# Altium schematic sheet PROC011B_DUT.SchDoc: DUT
size 431 x 279 mm; Date: Not shown in title block; ApprovedBy: Not shown in title block; CheckedBy: Not shown in title block; Author: Not shown in title block; CompanyName: Not shown in title block; Engineer: Not shown in title block; Organization: Not shown in title block; Address1: Not shown in title block; Address2: Not shown in title block; Address3: Not shown in title block; Address4: Not shown in title block; DocumentNumber: 1; Revision: Use project parameter SCH_Rev; SheetNumber: 2; SheetTotal: 17; PageSetup: Record=PageOptions¦CenterHorizontal=True¦CenterVertical=True¦PrintScale=0.64¦XCorrection=1.00¦YCorrection=1.00¦PrintKind=0¦BorderSize=5000000¦LeftOffset=0¦BottomOffset=0¦Orientation=2¦PaperLength=1000¦PaperWidth=1000¦Scale=100¦PaperSource=15¦PrintQuality=600¦MediaType=1¦DitherType=10¦PrintScaleMode=1¦PaperKind=Letter
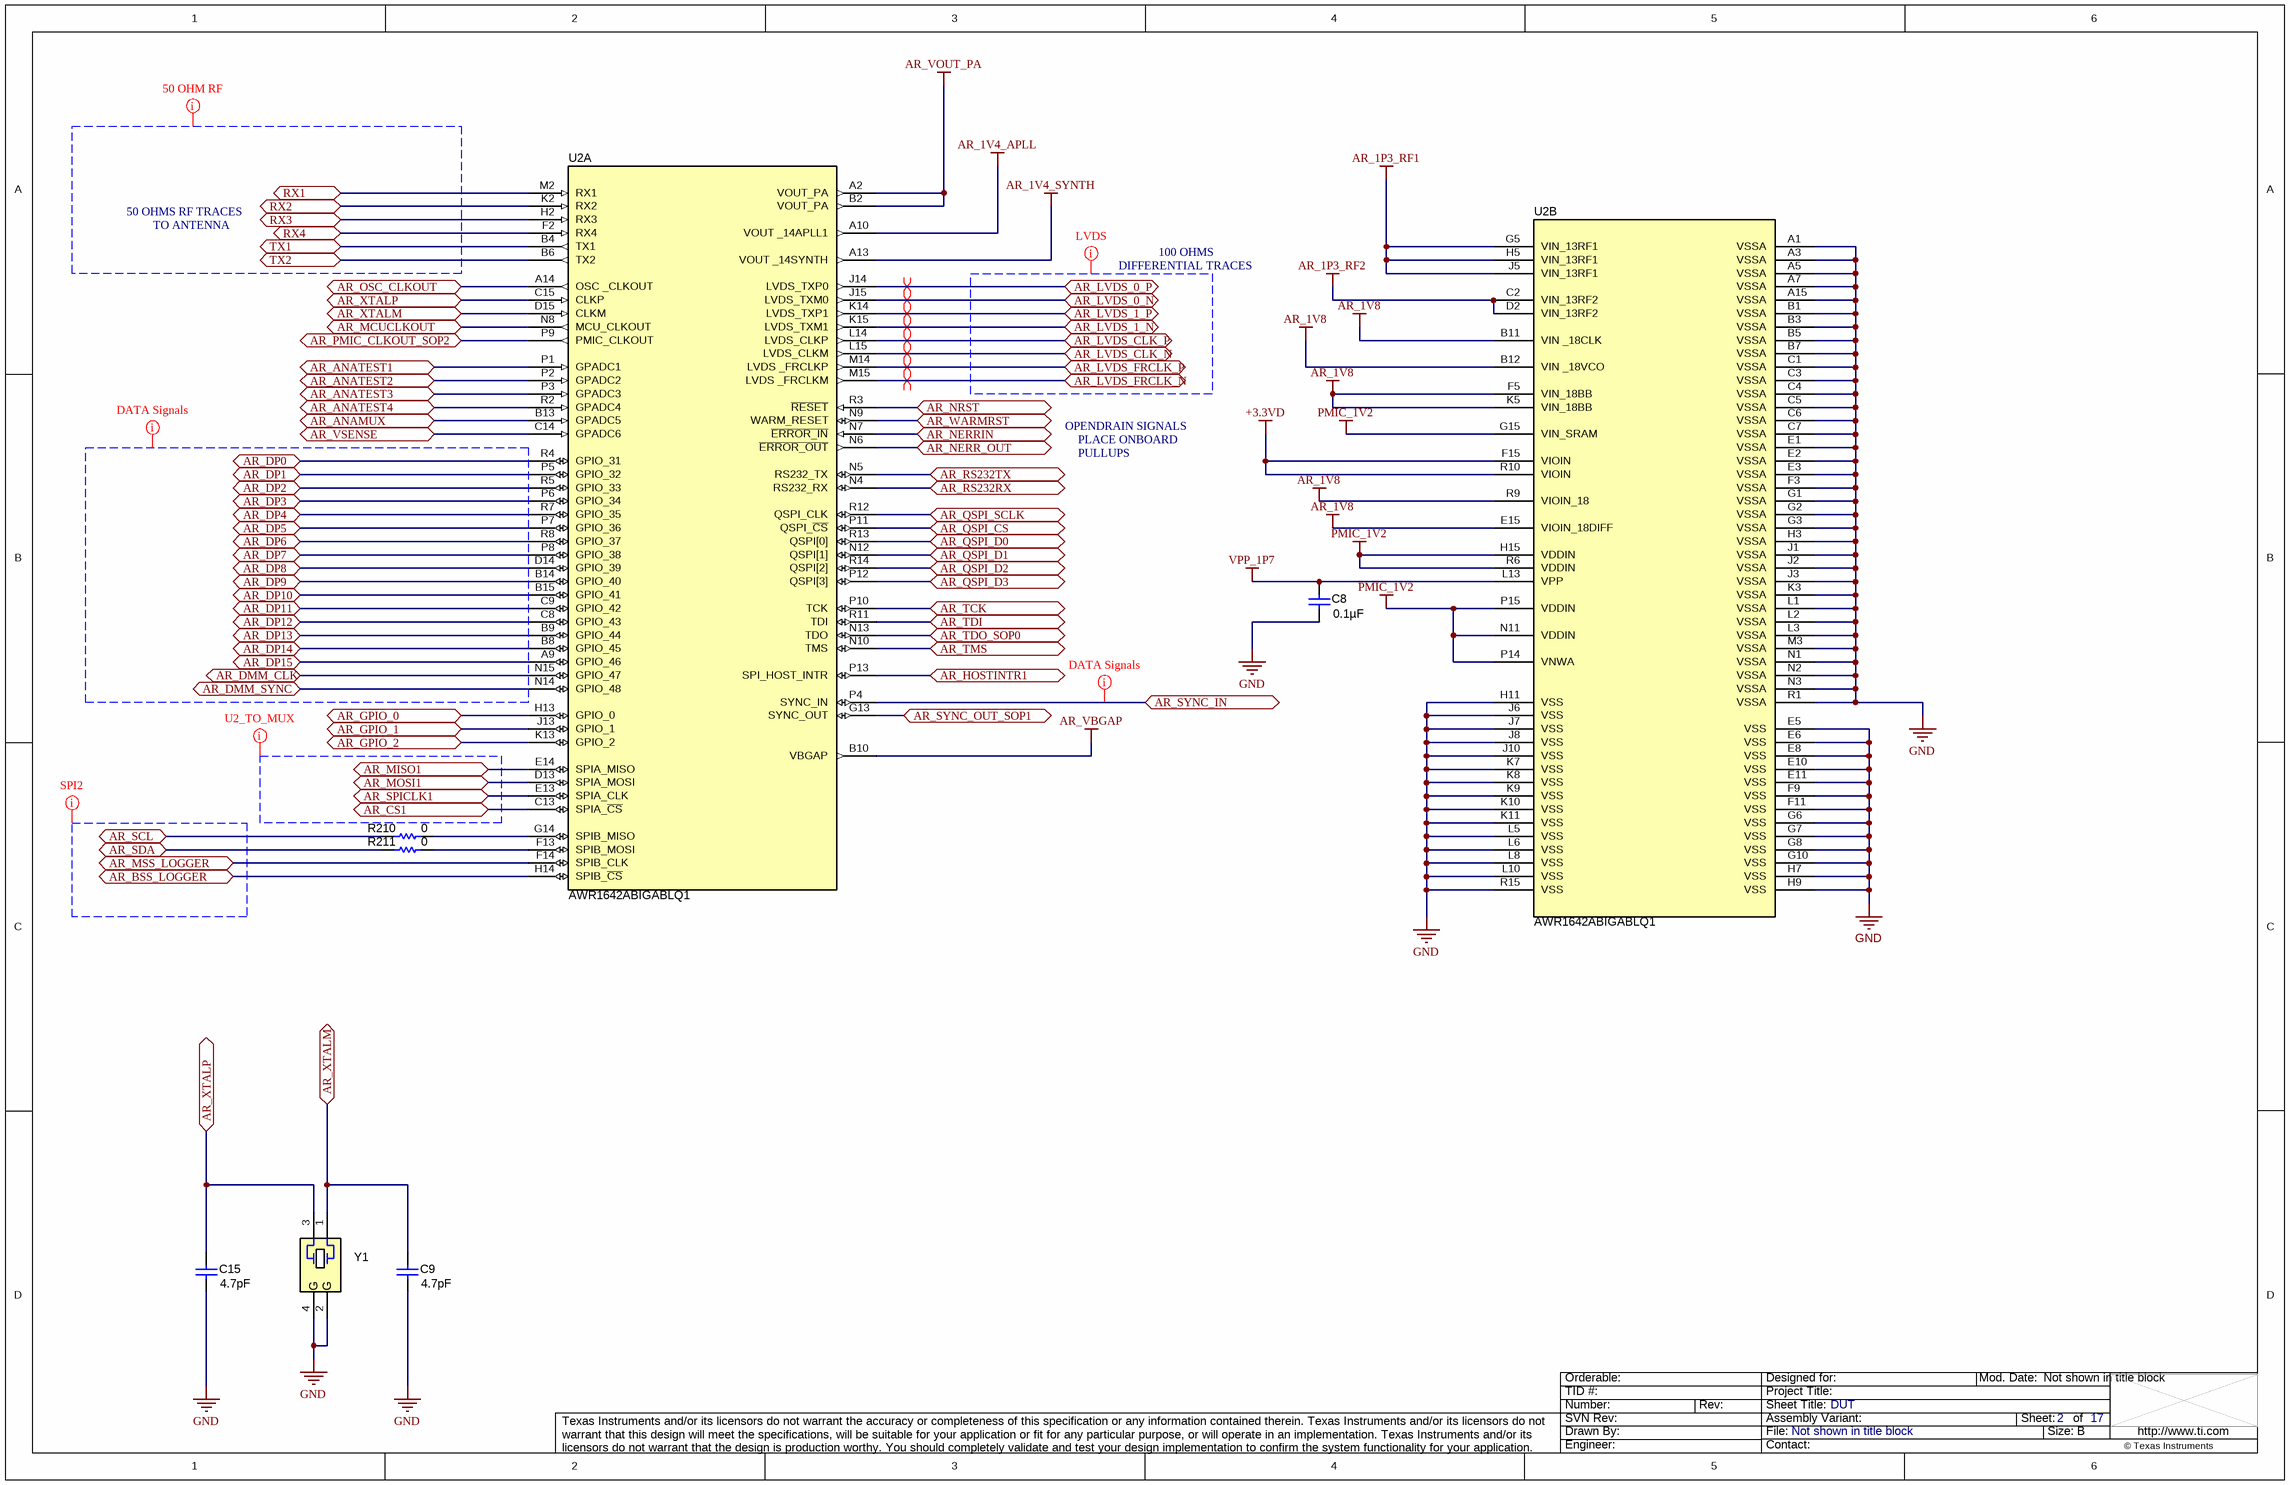
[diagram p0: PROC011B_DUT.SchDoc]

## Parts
C8  ValueDisplayed: 0.1µF  [0201_033]  (hidden comment: C0603X7S1A104K030BC)
C9  ValueDisplayed: 4.7pF  [0402L]  (hidden comment: GJM1555C1H4R7BB01D)
C15  ValueDisplayed: 4.7pF  [0402L]  (hidden comment: GJM1555C1H4R7BB01D)
R210  ValueDisplayed: 0  [0201]  (hidden comment: CRCW02010000Z0ED)
R211  ValueDisplayed: 0  [0201]  (hidden comment: CRCW02010000Z0ED)
U2  PartNumber: AWR1642ABIGABLQ1  [ABL0161B]  (hidden comment: X1642BIGABL)  (parts A,B of 2)
Y1  CX3225SA40000D0PTWCC  [Kyocera_CX3225SA]  (value not drawn)

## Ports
AR_ANAMUX, AR_ANATEST1, AR_ANATEST2, AR_ANATEST3, AR_ANATEST4, AR_BSS_LOGGER, AR_CS1, AR_DMM_CLK, AR_DMM_SYNC, AR_DP0, AR_DP1, AR_DP2, AR_DP3, AR_DP4, AR_DP5, AR_DP6, AR_DP7, AR_DP8, AR_DP9, AR_DP10, AR_DP11, AR_DP12, AR_DP13, AR_DP14, AR_DP15, AR_GPIO_0, AR_GPIO_1, AR_GPIO_2, AR_HOSTINTR1, AR_LVDS_0_N, AR_LVDS_0_P, AR_LVDS_1_N, AR_LVDS_1_P, AR_LVDS_CLK_N, AR_LVDS_CLK_P, AR_LVDS_FRCLK_N, AR_LVDS_FRCLK_P, AR_MCUCLKOUT, AR_MISO1, AR_MOSI1, AR_MSS_LOGGER, AR_NERR_OUT, AR_NERRIN, AR_NRST, AR_OSC_CLKOUT, AR_PMIC_CLKOUT_SOP2, AR_QSPI_CS, AR_QSPI_D0, AR_QSPI_D1, AR_QSPI_D2, AR_QSPI_D3, AR_QSPI_SCLK, AR_RS232RX, AR_RS232TX, AR_SCL, AR_SDA, AR_SPICLK1, AR_SYNC_IN, AR_SYNC_OUT_SOP1, AR_TCK, AR_TDI, AR_TDO_SOP0, AR_TMS, AR_VSENSE, AR_WARMRST, AR_XTALM, AR_XTALP, RX1, RX2, RX3, RX4, TX1, TX2

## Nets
+3.3VD: U2.F15(VIOIN) U2.R10(VIOIN)
AR_1P3_RF1: U2.G5(VIN_13RF1) U2.H5(VIN_13RF1) U2.J5(VIN_13RF1)
AR_1P3_RF2: U2.C2(VIN_13RF2) U2.D2(VIN_13RF2)
AR_1V4_APLL: U2.A10(VOUT__14APLL1)
AR_1V4_SYNTH: U2.A13(VOUT__14SYNTH)
AR_1V8: U2.B11(VIN__18CLK) U2.B12(VIN__18VCO) U2.E15(VIOIN_18DIFF) U2.F5(VIN_18BB) U2.K5(VIN_18BB) U2.R9(VIOIN_18)
AR_VBGAP: U2.B10(VBGAP)
AR_VOUT_PA: U2.A2(VOUT_PA) U2.B2(VOUT_PA)
GND: C8.1 C9.1 C15.1 U2.A1(VSSA) U2.A3(VSSA) U2.A5(VSSA) U2.A7(VSSA) U2.A15(VSSA) U2.B1(VSSA) U2.B3(VSSA) U2.B5(VSSA) U2.B7(VSSA) U2.C1(VSSA) U2.C3(VSSA) U2.C4(VSSA) U2.C5(VSSA) U2.C6(VSSA) U2.C7(VSSA) U2.E1(VSSA) U2.E2(VSSA) U2.E3(VSSA) U2.E5(VSS) U2.E6(VSS) U2.E8(VSS) U2.E10(VSS) U2.E11(VSS) U2.F3(VSSA) U2.F9(VSS) U2.F11(VSS) U2.G1(VSSA) U2.G2(VSSA) U2.G3(VSSA) U2.G6(VSS) U2.G7(VSS) U2.G8(VSS) U2.G10(VSS) U2.H3(VSSA) U2.H7(VSS) U2.H9(VSS) U2.H11(VSS) U2.J1(VSSA) U2.J2(VSSA) U2.J3(VSSA) U2.J6(VSS) U2.J7(VSS) U2.J8(VSS) U2.J10(VSS) U2.K3(VSSA) U2.K7(VSS) U2.K8(VSS) U2.K9(VSS) U2.K10(VSS) U2.K11(VSS) U2.L1(VSSA) U2.L2(VSSA) U2.L3(VSSA) U2.L5(VSS) U2.L6(VSS) U2.L8(VSS) U2.L10(VSS) U2.M3(VSSA) U2.N1(VSSA) U2.N2(VSSA) U2.N3(VSSA) U2.R1(VSSA) U2.R15(VSS) Y1.2(GND) Y1.4(GND)
PMIC_1V2: U2.G15(VIN_SRAM) U2.H15(VDDIN) U2.N11(VDDIN) U2.P14(VNWA) U2.P15(VDDIN) U2.R6(VDDIN)
VPP_1P7: C8.2 U2.L13(VPP)
AR_ANAMUX: U2.B13(GPADC5) ; port AR_ANAMUX
AR_ANATEST1: U2.P1(GPADC1) ; port AR_ANATEST1
AR_ANATEST2: U2.P2(GPADC2) ; port AR_ANATEST2
AR_ANATEST3: U2.P3(GPADC3) ; port AR_ANATEST3
AR_ANATEST4: U2.R2(GPADC4) ; port AR_ANATEST4
AR_BSS_LOGGER: U2.H14(SPIB_~{CS}) ; port AR_BSS_LOGGER
AR_CS1: U2.C13(SPIA_~{CS}) ; port AR_CS1
AR_DMM_CLK: U2.N15(GPIO_47) ; port AR_DMM_CLK
AR_DMM_SYNC: U2.N14(GPIO_48) ; port AR_DMM_SYNC
AR_DP0: U2.R4(GPIO_31) ; port AR_DP0
AR_DP1: U2.P5(GPIO_32) ; port AR_DP1
AR_DP2: U2.R5(GPIO_33) ; port AR_DP2
AR_DP3: U2.P6(GPIO_34) ; port AR_DP3
AR_DP4: U2.R7(GPIO_35) ; port AR_DP4
AR_DP5: U2.P7(GPIO_36) ; port AR_DP5
AR_DP6: U2.R8(GPIO_37) ; port AR_DP6
AR_DP7: U2.P8(GPIO_38) ; port AR_DP7
AR_DP8: U2.D14(GPIO_39) ; port AR_DP8
AR_DP9: U2.B14(GPIO_40) ; port AR_DP9
AR_DP10: U2.B15(GPIO_41) ; port AR_DP10
AR_DP11: U2.C9(GPIO_42) ; port AR_DP11
AR_DP12: U2.C8(GPIO_43) ; port AR_DP12
AR_DP13: U2.B9(GPIO_44) ; port AR_DP13
AR_DP14: U2.B8(GPIO_45) ; port AR_DP14
AR_DP15: U2.A9(GPIO_46) ; port AR_DP15
AR_GPIO_0: U2.H13(GPIO_0) ; port AR_GPIO_0
AR_GPIO_1: U2.J13(GPIO_1) ; port AR_GPIO_1
AR_GPIO_2: U2.K13(GPIO_2) ; port AR_GPIO_2
AR_HOSTINTR1: U2.P13(SPI_HOST_INTR) ; port AR_HOSTINTR1
AR_LVDS_0_N: U2.J15(LVDS_TXM0) ; port AR_LVDS_0_N
AR_LVDS_0_P: U2.J14(LVDS_TXP0) ; port AR_LVDS_0_P
AR_LVDS_1_N: U2.K15(LVDS_TXM1) ; port AR_LVDS_1_N
AR_LVDS_1_P: U2.K14(LVDS_TXP1) ; port AR_LVDS_1_P
AR_LVDS_CLK_N: U2.L15(LVDS_CLKM) ; port AR_LVDS_CLK_N
AR_LVDS_CLK_P: U2.L14(LVDS_CLKP) ; port AR_LVDS_CLK_P
AR_LVDS_FRCLK_N: U2.M15(LVDS__FRCLKM) ; port AR_LVDS_FRCLK_N
AR_LVDS_FRCLK_P: U2.M14(LVDS__FRCLKP) ; port AR_LVDS_FRCLK_P
AR_MCUCLKOUT: U2.N8(MCU_CLKOUT) ; port AR_MCUCLKOUT
AR_MISO1: U2.E14(SPIA_MISO) ; port AR_MISO1
AR_MOSI1: U2.D13(SPIA_MOSI) ; port AR_MOSI1
AR_MSS_LOGGER: U2.F14(SPIB_CLK) ; port AR_MSS_LOGGER
AR_NERR_OUT: U2.N6(~{ERROR_OUT}) ; port AR_NERR_OUT
AR_NERRIN: U2.N7(~{ERROR_IN}) ; port AR_NERRIN
AR_NRST: U2.R3(~{RESET}) ; port AR_NRST
AR_OSC_CLKOUT: U2.A14(OSC__CLKOUT) ; port AR_OSC_CLKOUT
AR_PMIC_CLKOUT_SOP2: U2.P9(PMIC_CLKOUT) ; port AR_PMIC_CLKOUT_SOP2
AR_QSPI_CS: U2.P11(QSPI_~{CS}) ; port AR_QSPI_CS
AR_QSPI_D0: U2.R13(QSPI[0]) ; port AR_QSPI_D0
AR_QSPI_D1: U2.N12(QSPI[1]) ; port AR_QSPI_D1
AR_QSPI_D2: U2.R14(QSPI[2]) ; port AR_QSPI_D2
AR_QSPI_D3: U2.P12(QSPI[3]) ; port AR_QSPI_D3
AR_QSPI_SCLK: U2.R12(QSPI_CLK) ; port AR_QSPI_SCLK
AR_RS232RX: U2.N4(RS232_RX) ; port AR_RS232RX
AR_RS232TX: U2.N5(RS232_TX) ; port AR_RS232TX
AR_SCL: R210.1 ; port AR_SCL
AR_SDA: R211.1 ; port AR_SDA
AR_SPICLK1: U2.E13(SPIA_CLK) ; port AR_SPICLK1
AR_SYNC_IN: U2.P4(SYNC_IN) ; port AR_SYNC_IN
AR_SYNC_OUT_SOP1: U2.G13(SYNC_OUT) ; port AR_SYNC_OUT_SOP1
AR_TCK: U2.P10(TCK) ; port AR_TCK
AR_TDI: U2.R11(TDI) ; port AR_TDI
AR_TDO_SOP0: U2.N13(TDO) ; port AR_TDO_SOP0
AR_TMS: U2.N10(TMS) ; port AR_TMS
AR_VSENSE: U2.C14(GPADC6) ; port AR_VSENSE
AR_WARMRST: U2.N9(WARM_RESET) ; port AR_WARMRST
AR_XTALM: C9.2 U2.D15(CLKM) Y1.1 ; port AR_XTALM
AR_XTALP: C15.2 U2.C15(CLKP) Y1.3 ; port AR_XTALP
RX1: U2.M2(RX1) ; port RX1
RX2: U2.K2(RX2) ; port RX2
RX3: U2.H2(RX3) ; port RX3
RX4: U2.F2(RX4) ; port RX4
TX1: U2.B4(TX1) ; port TX1
TX2: U2.B6(TX2) ; port TX2
NetR210_2: R210.2 U2.G14(SPIB_MISO)
NetR211_2: R211.2 U2.F13(SPIB_MOSI)

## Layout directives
differential pair: AR_LVDS_0_N, AR_LVDS_0_P, AR_LVDS_1_N, AR_LVDS_1_P, AR_LVDS_CLK_N, AR_LVDS_CLK_P, AR_LVDS_FRCLK_N, AR_LVDS_FRCLK_P
net class LVDS: (no net found under the mark)
net class DATA0-15: (no net found under the mark), AR_SYNC_IN
net class RF_RX&TX: (no net found under the mark)
net class SPI2: (no net found under the mark)
net class U2_TO_MUX: (no net found under the mark)

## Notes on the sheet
- 50 OHMS RF TRACES
- TO ANTENNA
- DIFFERENTIAL TRACES
- 100 OHMS
- OPENDRAIN SIGNALS
- PLACE ONBOARD
- PULLUPS

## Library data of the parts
C8 = CMP-0078219-1: CAP, CERM, 0.1 µF, 10 V,+/- 10%, X7S, 0201; Manufacturer: TDK; TaMin_C: -55°C; Polarized: N; Green_Lifecycle: NRND; SizeAreaWB_mm2: 2.08; Green_REACh: Passed; U/M: EA; Value: 0.1uF; TaMax_C: 125°C; SizeZ_mm: 0.33; SizeX_mm: 0.6; SizeY_mm: 0.3; Cap_Case: 0201; Value2: 10V; SizeArea_mm2: 0.18; CompType: Capacitor; Cap_F: 100nF; AEC Category: Q200
C9 C15 = CMP-0006367-2: CAP, CERM, 4.7 pF, 50 V, +/- 2%, C0G/NP0, 0402; Manufacturer: MuRata; TaMin_C: -55°C; Polarized: N; SizeAreaWB_mm2: 3; Value1: Unknown; U/M: EA; Value: 4.7pF; TaMax_C: 125°C; SizeZ_mm: 0.6; SizeX_mm: 1; SizeY_mm: 0.5; Cap_Case: 0402; Value2: 50V; CompType: Capacitor; AEC Category: Q200
R210 R211 = CMP-0027008-4: RES, 0, 5%, 0.05 W, 0201; Manufacturer: Vishay-Dale; Power_W: 50mW; TempCo: ppm/C; Value_Code: 0000; Value: 0; EIA_Code: E24; SizeX_mm: 0.6; SizeY_mm: 0.3; SizeZ_mm: 0.26; Value2: 0.05W; SizeArea_mm2: 0.18; CompType: Resistor; AEC Qualified: N; AEC Category: Q200; INSTALL: DNP
U2 = CMP-0077311-2: Single-Chip 77- and 79-GHz FMCW Radar Sensor, ABL0161B (FCBGA-161); Manufacturer: Texas Instruments; SizeX_mm: 10.4; CompType: IC; SizeZ_mm: 1.17; SizeArea_mm2: 108.16; SizeAreaWB_mm2: 153.76; U/M: EA
Y1 = CMP-0004694-3: Crystal, 40 MHz, 8pF, SMD; Manufacturer: Kyocera; TaMin_C: -40°C; Frequency Stability: +/-200ppm; SizeAreaWB_mm2: 14.7; Frequency_Fixed: 40MHz; TaMax_C: 125°C; SizeZ_mm: 0.8; SizeX_mm: 2.5; SizeY_mm: 3.2; SizeArea_mm2: 8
